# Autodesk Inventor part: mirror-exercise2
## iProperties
Author: Administrator
Created: 2000-12
Part Number: mirror-exercise2
Document SubType Name: Modeling
Designer: Administrator
Control State: 0
Master: False
Checked Out: False
PropertySet Name: Design Tracking Control
Shininess: 0.0
PropertySet Name: _Private Model Information
Density: 0.0
Volumn: 0.0
Area: 0.0
PropertySet Name: Model Information
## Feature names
1. Extrusion1
2. Extrusion2
3. Extrusion3
